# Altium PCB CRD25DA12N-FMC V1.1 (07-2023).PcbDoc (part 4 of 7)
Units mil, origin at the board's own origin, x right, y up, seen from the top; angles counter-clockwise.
Board outline 8000 x 8000 mil, 6 copper layers (Top Layer, Layer 2, Layer 3, Layer 4, Layer 5, Bottom Layer), stack 91 mil thick; 542 components, 315 nets, 1585 pads, 558 vias.
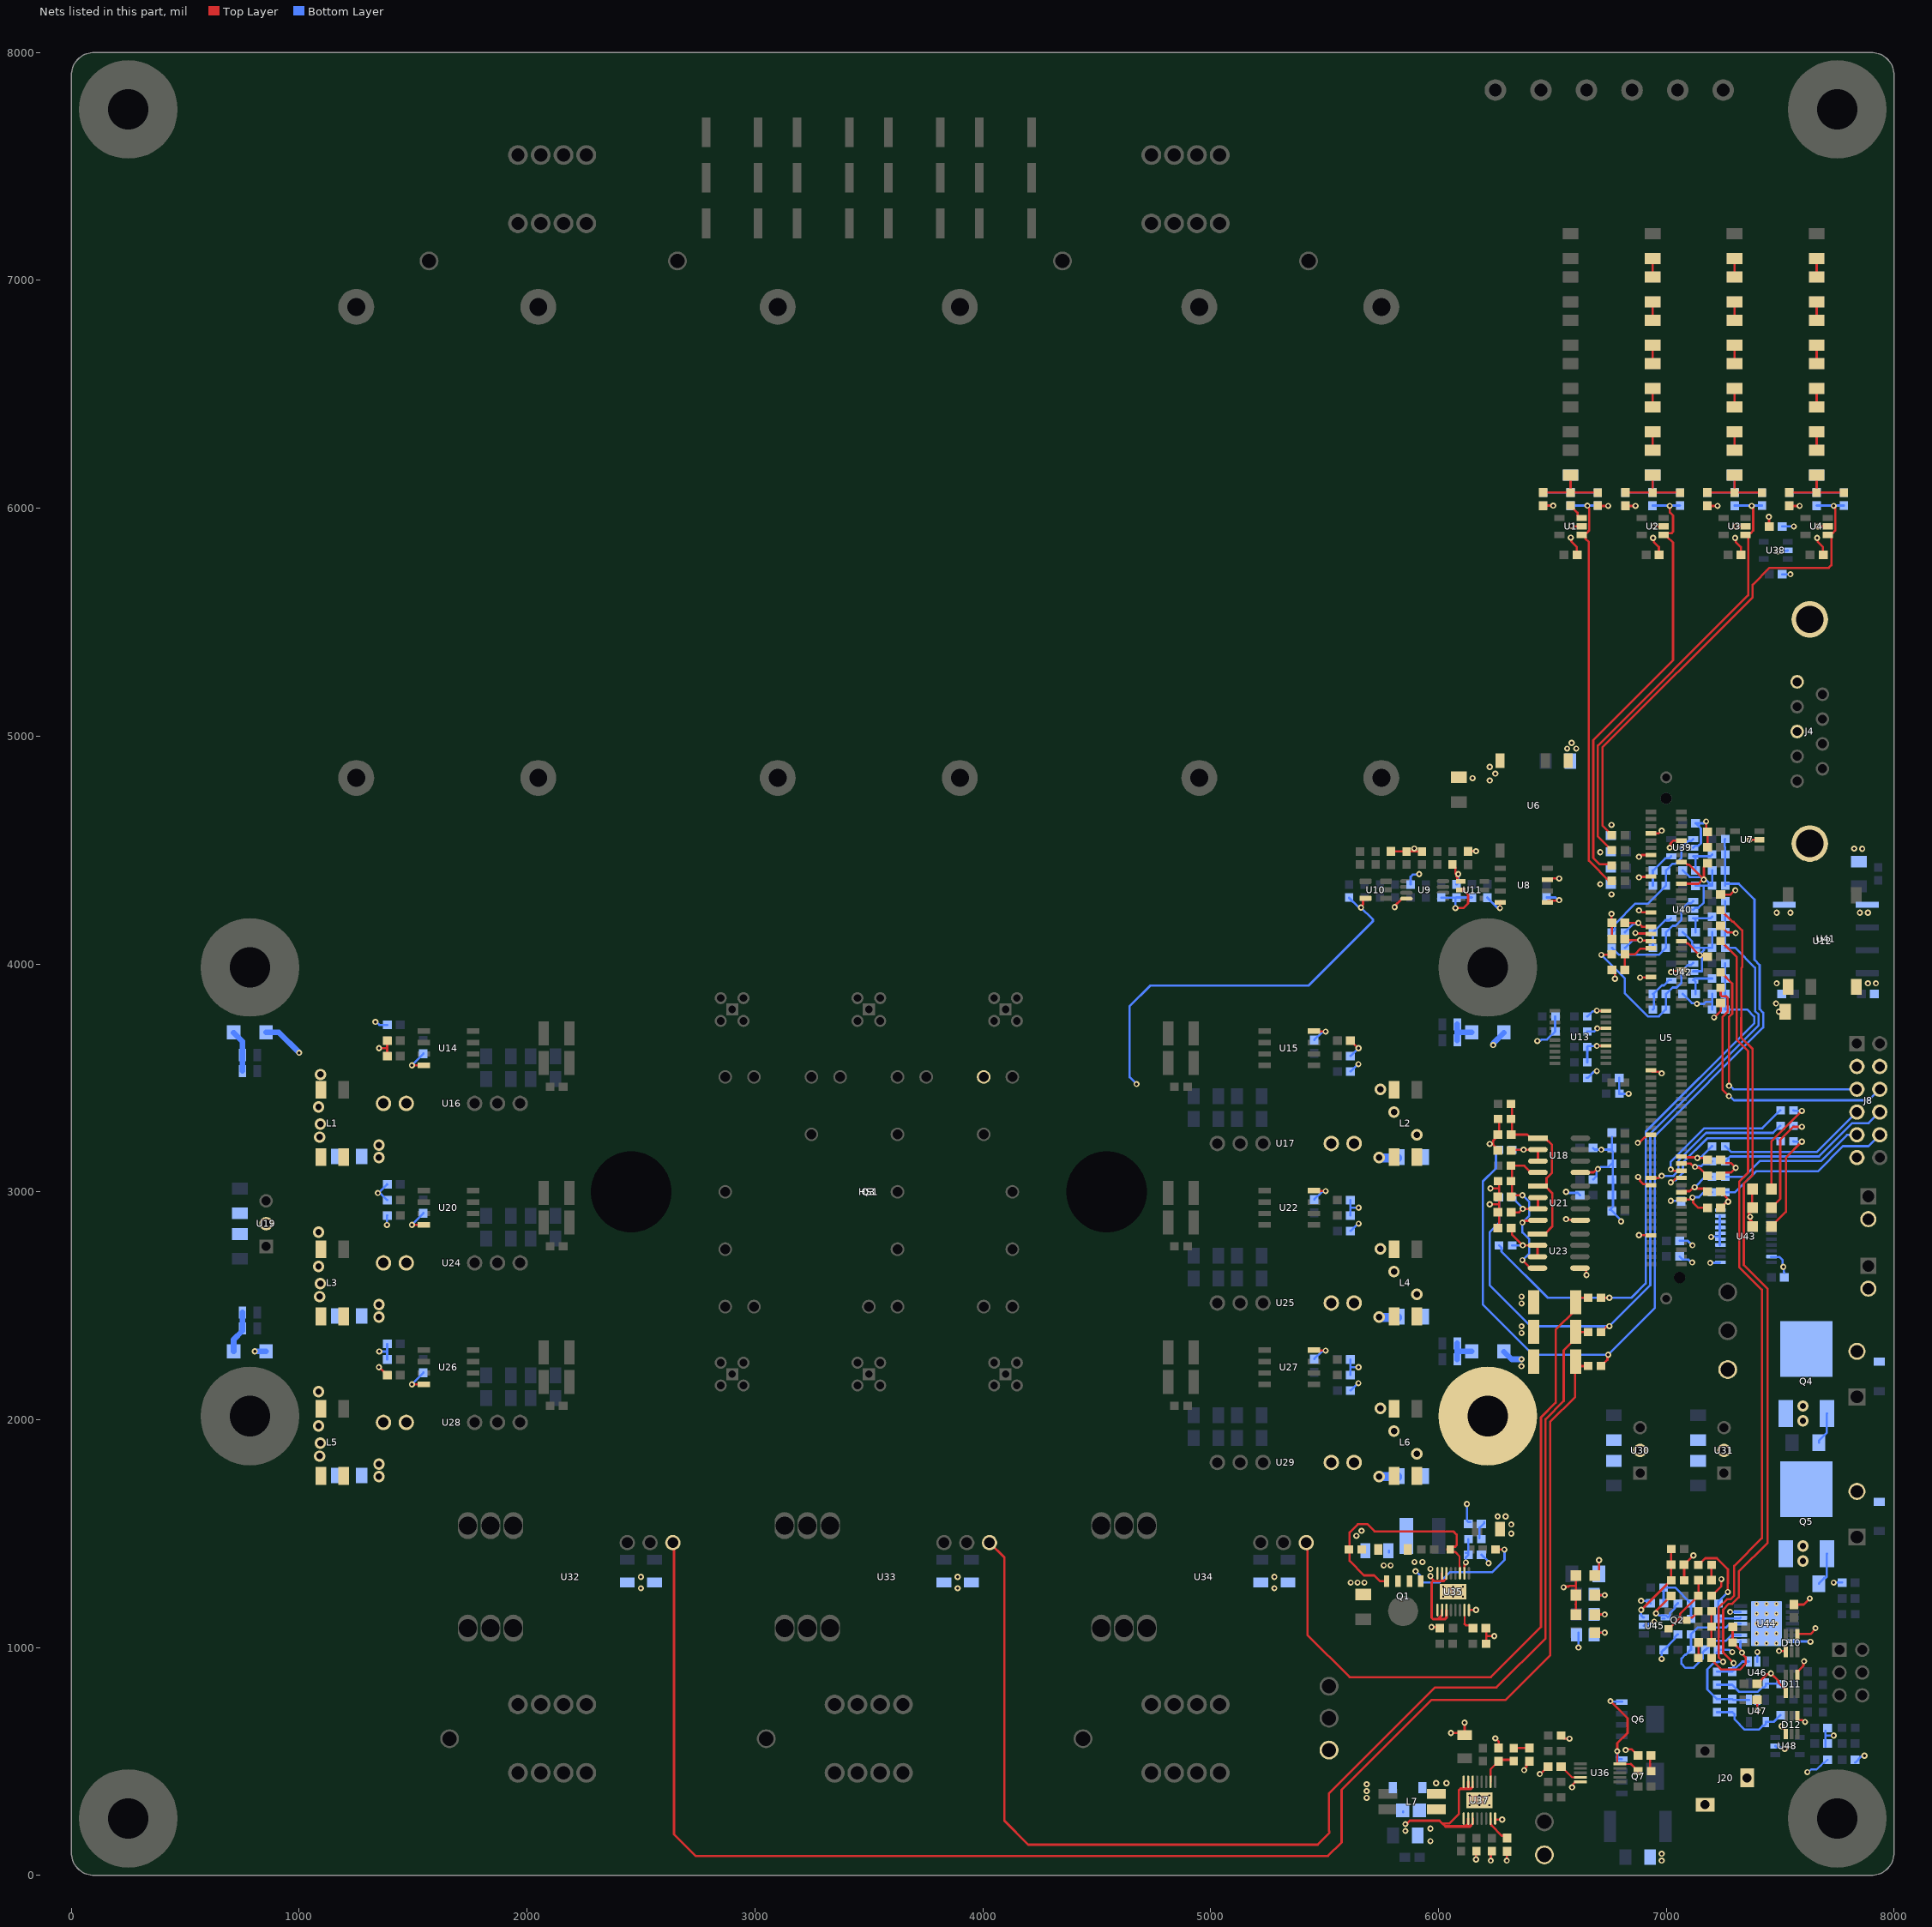
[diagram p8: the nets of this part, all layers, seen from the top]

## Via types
v1: diameter 27, hole 13, Top Layer to Bottom Layer, tented both sides, 455 vias
v2: diameter 50, hole 28, Top Layer to Bottom Layer, tented both sides, 76 vias
v3: diameter 19.68, hole 7.87, Top Layer to Bottom Layer, 27 vias

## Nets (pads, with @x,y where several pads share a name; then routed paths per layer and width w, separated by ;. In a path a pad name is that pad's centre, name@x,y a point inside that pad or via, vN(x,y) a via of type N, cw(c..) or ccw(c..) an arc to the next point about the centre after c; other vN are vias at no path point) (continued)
GND: C1.2 C2.2 C3.2 C4.2 C5.2 C6.2 C7.2 C8.2 C9.2 C11.2 C12.2 C15.2 C16.2 C17.2 C18.2 C19.2 C20.2 C21.2 C22.2 C23.2 C24.2 C25.2 C26.2 C27.2 C28.2 C29.2 C30.2 C31.2 C32.2 C33.2 C34.2 C35.2 C36.2 C37.2 C38.2 C40.2 C42.2 C44.2 C46.2 C47.2 C48.2 C49.2 C50.2 C51.2 C52.2 C53.2 C61.2 C62.2 C63.2 C64.2 C65.2 C66.2 C68.2 C69.2 C70.2 C72.2 C73.2 C77.2 C78.2 C79.2 C81.2 C83.2 C84.2 C85.2 C87.2 C88.2 C89.2 C90.2 C93.2 C94.2 C95.2 C102.2 C103.2 C104.2 C107.2 C108.2 C109.2 C110.2 C111.2 C112.2 C113.2 C114.2 C115.2 C116.2 C117.2 C118.2 C119.2 C120.2 C121.2 C124.2 C125.2 C126.2 C129.2 C132.2 C137.2 C138.2 C139.2 C140.2 C141.2 C142.2 C145.2 C148.2 C149.2 C154.2 C155.2 C158.2 C159.2 C160.2 C161.2 C162.1 C163.2 C164.1 C165.2 C166.1 C167.2 C169.2 C171.2 C172.2 C177.2 C179.2 C180.2 C181.2 C183.2 C184.2 D1.1 D2.1 D3.1 D6.1 D7.1 D8.1 D10.1 D10.4 D11.1 D11.4 D12.1 D12.4 D13.1 D14.1 D15.1 D16.1 D19.1 HS1.3 J8.3 J8.4 J8.11 J9.2 J10.2 J20.2 J20.3 L1.2 L2.2 L3.2 L4.2 L5.2 L6.2 Q4.3 Q5.3 R38.1 R67.1 R73.1 R84.1 R86.1 R90.1 R102.1 R103.1 R106.1 R109.1 R111.1 R120.1 R121.1 R164.1 R169.1 R174.1 R176.1 R177.1 R179.1 R180.1 R184.1 R187.1 R189.1 R216.1 R218.1 TP7.1 TP13.1 TP15.1 U1.2 U2.2 U3.2 U4.2 U5.7 U5.10 U5.13 U5.16 U5.19 U5.22 U5.29 U5.35 U5.38 U5.46 U5.47 U5.65 U5.83 U5.97 U5.111 U6.1 U7.2 U8.5 U8.7 U12.1 U13.4 U13.7 U13.10 U14.4 U15.4 U18.5 U19.2 U20.4 U21.5 U22.4 U23.5 U26.4 U27.4 U30.2 U31.2 U35.16 U35.17 U36.5 U37.16 U37.17 U38.2 U39.2 U40.2 U41.4 U42.2 U43.1 U43.4 U43.5 U43.6 U43.7 U43.8 U43.9 U43.10 U43.19 U44.6 U44.14 U44.15 U45.2 U46.2 U47.2 U48.2 | length 12079.2
  Top Layer w8: v1(6586.82,386.82) 6590.45,390.45 6590.45,400.31 U36.5@6599.86,409.72 ; U36.5@6600.77,410.63 U36.5@6622.91,410.63
  Top Layer w10: v1(1350,2230) 1351.47,2230 1385.47,2196 C36.2@1386.42,2196 ; v1(1350.35,3630) 1386.42,3630 ; C26.2@1385.47,3596 C26.2@1386.42,3596 1386.42,3630 ; C24.2@1386.42,3664 1386.42,3630 ; v1(1495,2155) U26.4@1546.73,2155 ; v1(1495,2855) U20.4@1546.73,2855 ; v1(1495,3555) U14.4@1546.73,3555 ; U27.4@5453.27,2305 5454.37,2303.9 5503.9,2303.9 v1(5505,2302.8) ; U22.4@5453.27,3005 5454.37,3003.9 5503.9,3003.9 v1(5505,3002.8) ; U15.4@5453.27,3705 5454.37,3703.9 5503.9,3703.9 v1(5505,3702.8) ; C25.2@5613.58,3664 5614.53,3664 5648.53,3630 v1(5649.65,3630) ; C40.2@5665,1241.25 C40.2@5670,1236.25 ; v1(5970,1090) 6001.38,1090 R106.1@6006.38,1085 ; v1(6055,625) 6111.73,625 6115,621.73 v1(6115,670) ; 6140,1165 v1(6165,1165) ; v1(6165,70) R120.1@6165,108.54 ; C44.2@6209.53,1085 6210,1084.53 6210,1049.76 ; R109.1@6210,1015 6210,1049.76 ; v1(6225,2945) 6265.42,2945 6266.42,2944 ; v1(6228.62,3014.86) 6263.54,3014.86 6266.38,3012.02 ; v1(6230,65) R121.1@6230,108.54 ; v1(6245,1050) 6244.76,1049.76 6210,1049.76 ; v1(6250,601.46) 6265,586.46 C49.2@6265,558.54 ; 6255,245 v1(6280,245) ; C35.2@6266.42,2840 6266.42,2944 ; R73.1@6266.38,3046 6266.38,3012.02 ; R67.1@6266.38,3319 6266.42,3318.96 6266.42,3251 6265.47,3251 6251.61,3237.14 6251.61,3236.19 6240.73,3225.3 6240.73,3206.75 6262.47,3185 C28.2@6275,3185 ; v1(6300,65) C53.2@6300,104.49 ; v1(6376.63,461.63) 6376.63,466.23 6386.14,475.74 6386.14,487.56 C50.2@6400,501.42 ; v1(6445,445) 6447.47,445 6480.47,478 C52.2@6481.42,478 ; C1.2@6460,6011.42 v1(6503.58,6011.42) ; U8.5@6478.35,4275 6480.85,4277.5 6527.5,4277.5 v1(6530,4280) ; U8.7@6478.35,4375 v1(6530,4375) v1@6531.12,4373.88 ; R111.1@6538.62,614 6551.58,601.04 6573.96,601.04 v1(6575,600) ; v1(6549.72,1264.16) 6552.97,1267.41 6572.61,1267.41 6575.2,1270 6601.16,1270 6603.66,1272.5 ; v1(6560,2880) 6562.53,2877.47 6620.58,2877.47 U21.5@6623.06,2875 ; v1(6580.67,5871.13) 6583.92,5867.88 6583.92,5853.71 6607.63,5830 6607.63,5795.95 C6.2@6608.58,5795 ; v1(6583.58,5921.42) 6584.29,5920.71 6627.52,5920.71 U1.2@6628.23,5920 ; U36.5@6599.86,409.72 U36.5@6600.77,410.63 ; 6601.16,1190 6603.66,1187.5 ; D8.1@6603.66,1145 6603.66,1187.5 ; D6.1@6603.66,1315 6603.66,1272.5 ; U23.5@6621.11,2665 6642.71,2665 6648.68,2659.03 6648.68,2636.32 v1(6650,2635) ; U18.5@6623.06,3085 6623.41,3085.36 6680.76,3085.36 6695.4,3100 v1(6700,3100) ; v1(6695,3640) 6695.3,3640.3 6734.7,3640.3 U13.4@6735,3640.59 ; v1(6695,3795) 6695.43,3794.57 6734.57,3794.57 U13.10@6735,3794.13 ; v1(6697.19,3717.36) U13.7@6735,3717.36 ; R38.1@6700,6011.38 6701.38,6010 v1(6745,6010) ; v1(6760,4220) 6760,4181.42 C17.2@6761.42,4180 C19.2@6761.42,4110 ; C21.2@6761.42,3974 6775,3960.42 v1(6775,3935) ; C2.2@6820,6011.42 6821.42,6010 v1(6865,6010) ; v1(6821.63,550.23) 6826.23,550.23 6830,554 6847.47,554 6875.47,526 C51.2@6876.42,526 ; v1(6864.55,4135.68) 6866.54,4133.69 6931.08,4133.69 U5.35@6933.07,4131.69 ; C51.2@6870.14,539.86 C51.2@6880,530 ; v1(6875,3215) 6878.25,3218.25 6884,3218.25 6904.89,3239.15 6908.64,3239.15 6919.29,3249.8 U5.83@6933.07,3249.8 ; v1(6876.5,3065) 6876.5,3060.4 6884.75,3052.15 6884.75,3048.22 6898.8,3034.17 6928.23,3034.17 U5.97@6933.07,3029.33 ; v1(6880,2810) 6880.57,2809.43 6929.43,2809.43 U5.111@6930,2810 ; v1(6880,4235) 6884.6,4235 6893.42,4226.18 U5.29@6933.07,4226.18 ; v1(6880,4380) 6881.83,4381.83 6931.24,4381.83 U5.19@6933.07,4383.66 ; v1(6880,4470) 6884.6,4470 6892.75,4478.15 U5.13@6933.07,4478.15 ; v1(6885,3940) 6885.47,3940.47 6934.53,3940.47 U5.47@6935,3940.94 ; U5.7@6933.07,4572.64 6966.29,4572.64 6978.65,4585 v1(6980,4585) ; U5.65@6935,3531.5 6939.84,3526.65 6968.75,3526.65 6975.4,3520 v1(6980,3520) ; v1(6942.09,5869.71) 6945.34,5866.45 6945.34,5852.28 6967.63,5830 6967.63,5795.95 C7.2@6968.58,5795 ; v1(6945,5920) U2.2@6988.23,5920 ; v1(7015,4510) 7018.25,4513.25 7018.25,4528.25 7031.14,4541.14 U5.10@7066.93,4541.14 ; v1(7021.31,3964.12) 7025.91,3964.12 7031.16,3969.37 7063.35,3969.37 U5.46@7067.64,3973.66 ; U5.38@7066.93,4100.2 7080.71,4100.2 7091.36,4089.54 7095.45,4089.54 v1(7147.18,4037.82) 7175.61,4037.82 C20.2@7181.42,4032 ; U5.22@7066.93,4352.17 7142.57,4352.17 7160.4,4370 v1(7165,4370) ; U5.16@7071.77,4451.5 U5.16@7066.93,4446.65 7080.71,4446.65 7091.36,4436 7099,4436 v1(7165,4370) ; v1(7118.8,1404.16) 7118.8,1402.28 7079.53,1363 C38.2@7078.58,1363 ; v1(7175,4625) 7175,4586.42 C11.2@7181.42,4580 C12.2@7181.42,4511 ; C3.2@7180,6011.42 7181.42,6010 v1(7225,6010) ; C15.2@7181.42,4442 7180.47,4442 7166.61,4428.14 7166.61,4427.19 7165,4425.58 v1(7165,4370) ; R103.1@7198.62,1227 7199.53,1227 7241.89,1269.36 v1(7241.89,1300) ; v1(7210,3765) 7240,3795 7240,3826.58 C22.2@7238.58,3828 ; C33.2@7238.58,2930 7239.53,2930 7262.82,2953.29 7268.25,2953.29 v1(7271.5,2956.54) 7268.25,2959.8 7268.25,2971.28 7239.53,3000 C31.2@7238.58,3000 ; C30.2@7238.58,3070 7235,3070 7230,3075 7238.86,3083.86 7283.86,3083.86 v1(7305,3105) 7283.86,3126.14 7252.44,3126.14 C29.2@7238.58,3140 ; C18.2@7238.58,4168 7239.53,4168 7269.27,4138.25 7301.75,4138.25 v1(7305,4135) ; C16.2@7238.58,4304 7281.99,4304 7301.26,4323.27 v1(7303.03,4323.27) ; v1(7302.09,5869.71) 7305.34,5866.45 7305.34,5852.28 7327.63,5830 7327.63,5795.95 C8.2@7328.58,5795 ; v1(7305,5920) U3.2@7348.23,5920 ; v1@7360.04,2893.32 7360,2893.28 7360,2885 D3.1@7375,2870 ; v1@7361.75,2883.25 v1(7368.5,2890) 7361.26,2897.24 7361.26,2911.38 7361.51,2911.63 D2.1@7372.7,2911.63 ; v1(7365,4545) U7.2@7408.15,4545 ; D2.1@7365.51,2949.17 7367.17,2949.17 D2.1@7367.17,2950.83 ; D2.1@7375,2948.66 7376.34,2950 D1.1@7376.34,3029.21 ; C47.2@7398.58,771 7400,769.58 v1(7400,725) ; C46.2@7398.58,840 7399.53,840 7442.79,883.26 7455.9,883.26 v1(7459.15,886.52) 7492.63,853.04 7492.63,846.19 7524.41,814.41 D11.1@7524.41,800.63 ; v1(7450,5962.36) 7451.14,5961.23 C5.2@7451.14,5920 ; v1(7495,985) 7520.55,985 7524.41,981.14 D10.1@7524.41,980.63 ; v1(7506,655.26) 7506,652.82 7520.55,638.27 D12.1@7520.55,625 ; C4.2@7540,6011.42 7541.42,6010 v1(7585,6010) ; C42.2@7560,1188.58 7603.58,1188.58 v1(7630,1215) ; D12.4@7575.59,699.37 7575.59,685.59 7579.45,681.73 7597.67,681.73 7605.4,674 v1@7610,674 ; D11.4@7575.59,879.37 7575.59,893.15 7601.75,919.31 7601.75,936.75 v1(7605,940) ; D10.4@7575.59,1059.37 7633.25,1059.37 7655,1081.12 v1(7655,1085) ; v1(7662.09,5869.71) 7665.34,5866.45 7665.34,5852.28 7687.63,5830 7687.63,5795.95 C9.2@7688.58,5795 ; v1(7665,5920) U4.2@7708.23,5920 ; 6266.42,2944 6266.42,2978 6266.38,2978.04 6266.38,3012.02 ; 6603.66,1187.5 D7.1@6603.66,1230 6603.66,1272.5 ; C38.2@7078.58,1363 R102.1@7078.62,1295 R102.1@7078.62,1295 C38.2@7078.58,1363
  Bottom Layer w8: v1@7623.76,452.95 7635.81,465 7660,465 7674.14,479.14 7675.38,479.14 7681.24,485 7681.24,486.24 7688.14,493.14 7693.71,493.14 C181.2@7708.58,508
  Bottom Layer w10: v1(1334.48,3745.52) 1338.09,3745.52 1351.61,3732 C87.2@1386.42,3732 ; v1(1351.47,2299.13) 1385.3,2299.13 1386.42,2298 ; v1(1385,2854.54) 1385,2894.58 C120.2@1386.42,2896 ; C137.2@1385.47,2332 C137.2@1386.42,2332 1386.42,2298 ; C138.2@1386.42,2264 1386.42,2298 ; C115.2@1386.42,2964 1385.47,2964 1357.73,2991.75 1348.25,2991.75 v1(1345,2995) 1348.47,2995 1385,3031.53 1385,3033.42 C110.2@1386.42,3032 ; v1(1495,2155) 1495,2155.47 1545,2205.47 C141.2@1545,2206.42 ; v1(1495,2855) 1495,2855.47 1545,2905.47 C118.2@1545,2906.42 ; v1(1495,3555) 1495,3555.47 1545,3605.47 C89.2@1545,3606.42 ; C140.2@5455,2265.58 5455,2266.53 5488.02,2299.54 5501.75,2299.54 v1(5505,2302.8) ; C117.2@5455,2965.58 5455,2966.53 5488.02,2999.54 5501.75,2999.54 v1(5505,3002.8) ; C88.2@5455,3665.58 5455,3666.53 5488.02,3699.54 5501.75,3699.54 v1(5505,3702.8) ; C145.2@5613.58,2128 5614.53,2128 5646.53,2160 v1(5649.05,2160) ; C142.2@5613.58,2196 5613.58,2230 ; C139.2@5613.58,2264 5613.58,2230 ; C124.2@5613.58,2828 5614.53,2828 5646.53,2860 v1(5650,2860) ; C121.2@5613.58,2896 5613.58,2930 ; C116.2@5613.58,2964 5613.58,2930 ; C93.2@5613.58,3528 5614.53,3528 5646.53,3560 v1(5649.05,3560) ; C90.2@5613.58,3596 5614.53,3596 5648.53,3630 v1(5649.65,3630) ; v1(5649.65,2230) 5649.5,2230.15 5621.15,2230.15 5621,2230 5613.58,2230 ; v1(5649.85,2930.15) 5649.69,2930 5613.58,2930 ; v1(6125,1630) 6125,1556.86 6131.51,1550.35 C158.2@6139.73,1550.35 ; C160.2@6188.58,1407 6189.53,1407 6216.75,1379.78 6216.75,1373.25 v1(6220,1370) ; D15.1@6287.4,2298.03 D15.1@6287.4,2300 ; D13.1@6287.4,3698.03 D13.1@6287.4,3700 ; D15.1@6311.93,2273.5 D15.1@6313.9,2273.5 ; v1@6361.45,2237.96 v1(6364.7,2234.7) ; v1(6433.85,3661.83) 6437.11,3665.08 6449.78,3665.08 6453.19,3668.5 6476.84,3668.5 6511.34,3703 6512.24,3703 R177.1@6512.24,3770 ; C73.2@6475,4291.42 6513.98,4291.42 6525.4,4280 v1(6530,4280) ; v1(6560,3000) 6564.6,3000 6569.6,2995 6611.42,2995 C114.2@6621.42,2985 ; v1@6583.57,390.07 v1(6586.82,386.82) ; R216.1@6614.49,1065 6615,1064.49 v1(6615,1000) ; C95.2@6650,3500 6654.53,3500 6681.27,3526.75 6691.75,3526.75 v1(6695,3530) ; R187.1@6653.62,3568 R184.1@6653.62,3636 6657.62,3640 v1(6695,3640) ; R179.1@6653.62,3703 6682.82,3703 v1(6697.19,3717.36) ; R176.1@6653.62,3770 6654.53,3770 6676.27,3791.75 6691.75,3791.75 v1(6695,3795) ; C109.2@6678.58,3054 6679.53,3054 6693.39,3067.86 6693.39,3088.79 6700,3095.4 v1(6700,3100) 6704.6,3100 6713.74,3109.14 6747.56,3109.14 C107.2@6761.42,3123 ; C104.2@6678.58,3192 6685.58,3185 v1(6715,3185) 6756.46,3185 C103.2@6761.46,3180 ; 6761.46,3240 C103.2@6761.46,3180 ; C94.2@6793.58,3500 R189.1@6793.62,3430 R189.1@6793.62,3430 v1(6835,3430) ; v1(6801.5,2870) 6798.25,2873.25 6798.25,2879.13 6756.07,2921.3 6752.76,2921.3 6766.46,2935 6766.46,3055.63 6765,3057.09 6765,3176.46 C103.2@6761.46,3180 ; v1(6889.85,1205.15) 6920.27,1205.15 C169.2@6931.42,1194 ; U45.2@6901.77,1095 6910.55,1103.78 6932.8,1103.78 6942.81,1113.79 v1(6947.41,1113.79) ; v1(6980,950) 6980,981.42 C172.2@6988.58,990 6989.53,990 7037.52,1037.99 7037.52,1045.04 7050.47,1058 R218.1@7051.38,1058 ; v1(7019.81,2960) 7062.85,2960 C111.2@7065,2957.85 ; C129.2@7058.58,2716 7072.44,2702.14 7097.31,2702.14 7109.45,2690 v1(7114.05,2690) ; C126.2@7058.58,2785 7094.69,2785 7114.69,2765 v1(7115,2765) ; C85.2@7071.42,3868 7072.37,3868 7112.12,3828.25 7131.75,3828.25 v1(7135,3825) 7166,3825 7175.02,3834.02 7201.42,3834.02 ; C79.2@7071.42,4139 7072.37,4139 7113.76,4097.61 7113.76,4083.86 7127.63,4070 C81.2@7128.58,4070 7164.98,4070 ; C70.2@7071.42,4411 7072.37,4411 7102.24,4381.14 7150.33,4381.14 7161.47,4370 v1(7165,4370) 7168.25,4366.75 7176.73,4366.75 R164.1@7200.47,4343 ; U42.2@7118.23,3967 7119.23,3968.01 7156.78,3968.01 7156.78,4023.62 7147.18,4033.22 v1(7147.18,4037.82) 7147.18,4042.42 7164.98,4060.21 7164.98,4070 ; U40.2@7118.23,4238 7127.01,4246.78 7141.58,4246.78 7164.52,4269.72 7164.52,4343 ; U39.2@7118.23,4510 7127.01,4518.78 7141.58,4518.78 7151.87,4529.07 7151.87,4594.66 C64.2@7129.53,4617 ; C77.2@7128.58,4343 7164.52,4343 ; C64.2@7128.58,4617 C64.2@7129.53,4617 ; v1(7175,4625) 7170.4,4625 7162.4,4617 C64.2@7129.53,4617 ; v1(7193.1,2688.1) 7193.46,2688.46 7234.64,2688.46 U43.1@7235,2688.82 ; v1(7196.63,2801.63) 7198.98,2803.98 7235,2803.98 ; R174.1@7201.38,3800 R174.1@7201.38,3800 7201.42,3834.02 ; C84.2@7201.42,3868 7201.42,3834.02 ; C78.2@7201.42,4139 C78.2@7201.42,4139 R169.1@7201.38,4070 7164.98,4070 ; C69.2@7201.42,4411 C69.2@7201.42,4411 R164.1@7201.38,4343 R164.1@7200.47,4343 ; C171.2@7220.28,975.24 C171.2@7230.05,985 ; C171.2@7228.58,990 7275.4,990 7285.4,980 v1(7290,980) ; U43.4@7235,2765.59 7235,2803.98 ; U43.9@7235,2893.54 7235,2803.98 ; U43.10@7235,2919.13 7246.97,2919.13 7249.85,2922.01 7249.85,2939.85 7252.01,2942.01 7252.36,2942.01 7266.9,2956.54 v1(7271.5,2956.54) ; v1(7280.29,1156.3) 7280.35,1156.24 U44.6@7325.83,1156.18 U44.6@7325.83,1156.18 ; v1(7400,725) U47.2@7400,770 ; U46.2@7400,938.23 v1(7400,980) ; U43.19@7459.41,2714.41 7495.59,2714.41 7510.88,2699.12 7510.88,2673.19 v1(7513.45,2670.62) 7516.7,2667.37 7516.7,2646.84 7518.54,2645 ; U48.2@7478.7,567.6 7485.51,560.79 7509.61,560.79 7515.4,555 v1(7520,555) ; v1(7490,5810) 7492.5,5812.5 7530.65,5812.5 U38.2@7533.15,5815 ; C62.2@7508.58,5710 v1(7545,5710) ; C61.2@7508.58,5920 v1(7560,5920) ; U44.14@7554.17,1028.23 7555.63,1026.77 7631.32,1026.77 v1(7632.78,1025.32) ; v1(7619.16,452.95) v1@7623.76,452.95 ; C179.2@7698.58,565 7698.58,599.5 ; C177.2@7698.58,634 7698.58,616.75 ; 7699.08,600 7698.58,599.5 ; v1(7734.95,613.44) 7701.89,613.44 7698.58,616.75 ; v1(7735,1285) C167.2@7771.42,1285 ; C180.2@7828.58,495 7829.53,495 7856.27,521.75 7866.75,521.75 v1(7870,525) ; 7164.52,4343 R164.1@7200.47,4343 ; 7698.58,599.5 7698.58,616.75
  Bottom Layer w25: v1(805,2300) D16.1@854.33,2300 ; D14.1@854.33,3700 910,3700 v1(1000,3610) ; v1(6240.35,3644.22) 6240.73,3644.6 6240.73,3651.36 D13.1@6287.4,3698.03 ; D15.1@6287.4,2298.03 D15.1@6311.93,2273.5 ; D15.1@6313.9,2273.5 6322.4,2265 v1(6365,2265)
  other v1: 6980,65 6980,95 5965,150 5965,205 5685,340 5685,370 5685,400 7609.25,673.1 2500,1260 3890,1260 5280,1260 5615,1285 5645,1285 5675,1285 2500,1310 3890,1310 5280,1310 5639.85,1490.15 6320,1500 5662.8,1512.2 6320,1540 6260,1575 6295,1575 6365,2380 6364.85,2409.85 6365,2510 6365,2540 6225,3210 7494.21,3790 7481.72,3826.72 7485,3915 7485,4225 7545,4225 6760,4305 6710,4350 6710,4490 6760,4610 6565,4945 6605,4945 6585,4970
  other v2: 7600,1380 7600,1445 5805,1950 1085,1972 7600,1994.76 5745,2050 7600,2059.76 1085,2123 5805,2650 1085,2672 5745,2750 1085,2823 5805,3350 1085,3372 5745,3450 1093.14,3514.86
  other v3: 6136.69,308.35 6180,308.35 6223.31,308.35 6136.69,351.65 6180,351.65 6223.31,351.65 7396.69,1018.39 7440,1018.39 7483.31,1018.39 7396.69,1061.69 7440,1061.69 7483.31,1061.69 7396.69,1105 7440,1105 7483.31,1105 7396.69,1148.31 7440,1148.31 7483.31,1148.31 7396.69,1191.61 7440,1191.61 7483.31,1191.61 6021.69,1223.35 6065,1223.35 6108.31,1223.35 6021.69,1266.65 6065,1266.65 6108.31,1266.65
GND_ISO: C67.2 C82.2 J4.3 J4.5 J4.10 J4.11 U12.4 U41.5
  other v1: 7885,3915 7920,3915 7850,4225 7885,4225 7860,4505 7824.6,4506.19
GND_NTC: C10.2 C13.2 C14.2 C74.2 C75.2 C76.2 Q3.NTC1 R49.1 R50.1 R157.1 R159.1 R163.1 U6.4 U8.4 U9.4 U10.5 U11.2 | length 2565.5
  Top Layer w10: v1(5660.12,4247.58) 5660.12,4252.18 5668.94,4261 5668.94,4280.98 5675.55,4287.6 U10.5@5689.92,4287.6 ; C13.2@5792,4493.58 R49.1@5860,4493.62 R49.1@5860,4493.62 v1@5894,4493.62 ; v1(5808.01,4249.02) 5811.27,4252.27 5811.27,4257.51 5837.96,4284.2 5856.88,4284.2 U9.4@5859.29,4286.61 ; v1(5894,4506.31) v1@5894,4493.62 ; R50.1@5928,4493.62 v1@5894,4493.62 ; v1(6075,4245) 6110.4,4245 6130.49,4265.09 6130.49,4303.17 6108.66,4325 U11.2@6098.82,4325 ; C14.2@6130,4493.58 6131.42,4495 v1(6165,4495) ; v1(6270,4245) 6270,4273.35 U8.4@6271.65,4275
  Bottom Layer w10: v1(4675,3472.73) 4645,3502.73 4645,3815 4735,3905 5430,3905 5712.21,4187.21 5712.21,4195.49 5656.87,4250.83 5647.64,4250.83 5608,4290.47 R163.1@5608,4291.38 ; R159.1@5878,4348.62 5878,4382.48 5887.25,4391.73 5913.47,4391.73 v1(5915.75,4394.02) ; R157.1@6012,4291.38 C76.2@6079,4291.42 ; v1(6075,4245) 6075,4287.42 C76.2@6079,4291.42 ; C75.2@6147,4291.42 C76.2@6079,4291.42 C76.2@6079,4291.42 ; C74.2@6225,4281.42 C74.2@6215,4291.42 6215,4290.47 6257.22,4248.25 6266.75,4248.25 v1(6270,4245)
  other v1: 6225,4805 6150,4815 6250,4835 6225,4865
GPIO35: C29.1 R193.2 U5.90 | length 202.3
  Top Layer w10: U5.90@7066.93,3155.31 7070.74,3151.5 v1@7133.49,3151.51 ; v1(7136.75,3148.25) 7173.17,3148.25 C29.1@7181.42,3140
  Bottom Layer w10: v1(7136.75,3148.25) 7140,3151.51 7151.98,3151.51 7200.47,3200 R193.2@7201.38,3200
GPIO44: C30.1 R195.2 U5.92 | length 222
  Top Layer w10: U5.92@7066.93,3123.82 7106.98,3123.82 7121.23,3109.57 v1(7125.83,3109.57) 7129.08,3106.32 7144.15,3106.32 7180.47,3070 C30.1@7181.42,3070
  Bottom Layer w10: v1(7125.83,3109.57) 7129.08,3112.83 7154.15,3112.83 7161.37,3120.04 7188.42,3120.04 R195.2@7201.38,3133
GPIO54: C31.1 R196.2 U5.100 | length 227.4
  Top Layer w10: U5.100@7066.93,2997.83 7071.77,3002.68 7103.08,3002.68 7120.4,3020 v1(7125,3020) 7129.6,3020 7135.74,3013.86 7167.56,3013.86 C31.1@7181.42,3000
  Bottom Layer w10: v1(7125,3020) 7171,3066 R196.2@7201.38,3066
GPIO55: C33.1 R197.2 U5.102 | length 232.1
  Top Layer w10: U5.102@7066.93,2966.34 7101.74,2966.34 ; v1@7118.25,2978.25 v1(7115,2975) 7118.25,2971.75 7118.25,2951.75 7140,2930 C33.1@7181.42,2930
  Bottom Layer w10: v1(7115,2975) 7116.44,2976.44 7143.5,2976.44 7165.06,2998 R197.2@7201.38,2998
HI_OC_REF: C27.1 R66.1 R67.2 U18.1 U21.1 U23.1 | length 820.8
  Top Layer w10: R66.1@6323.62,3386 6323.62,3319 6323.62,3251.04 6323.58,3251 6389.7,3251 6405.7,3235 U18.1@6436.94,3235 6468.19,3235 6498.19,3205 6498.19,3083.24 6474.64,3059.7 6474.64,3031.46 U21.1@6468.19,3025 ; U23.1@6435,2815 6466.24,2815 6500,2848.76 6500,2993.19 U21.1@6468.19,3025 ; U21.1@6436.94,3025 U21.1@6468.19,3025
IU: R90.2 R93.1 U32.9 | length 7064.2
  Top Layer w10: U32.9@2640,1460 2645,1455 2645,180 2740,85 5515,85 5575,145 5575,375 5970,770 6295,770 6490,965 6490,1990 6600,2100 6600,2252.48 R90.2@6602.52,2255 ; R90.2@6602.52,2254.61 6622.13,2235 R93.1@6656.38,2235
IU_FILT: C69.1 R93.2 R154.1 R155.1 R164.2 R194.1 | length 4074.7
  Top Layer w10: R93.2@6713.62,2235 6714.53,2235 6741.75,2262.22 6741.75,2281.75 v1(6745,2285)
  Bottom Layer w10: R194.1@6265.47,3185 6252.52,3172.04 6252.52,3102.52 6195,3045 6195,2505 6415,2285 v1(6745,2285) 6950,2490 6950,3245.31 7425.71,3721.02 7425.71,3785.85 7410,3801.57 7410,3995 7387,4018 7387,4283 7318.23,4351.77 7260.39,4351.77 R164.2@7258.62,4350 ; R164.2@7258.62,4343 R164.2@7258.62,4350 ; R154.1@7258.62,4548 7255.96,4545.33 7255.96,4515.04 7258.62,4512.38 R155.1@7258.62,4480 R155.1@7258.62,4480 C69.1@7258.58,4411 C69.1@7258.58,4411 R164.2@7258.62,4350
IU_MEAS: C17.1 R168.2 U5.33 | length 197.7
  Top Layer w10: C17.1@6818.58,4180 v1(6877.48,4180) 6894.45,4163.03 U5.33@6933.39,4163.03
  Bottom Layer w10: R168.2@6818.62,4139 6819.53,4139 6857.27,4176.75 6874.22,4176.75 v1(6877.48,4180)
IV: R86.2 R87.1 U33.9 | length 5597.3
  Top Layer w10: U33.9@4030,1460 4095,1395 4095,240 4200,135 5470,135 5520.86,185.86 5520.86,194.14 5520,195 5520,360 5985,825 6255,825 6470,1040 6470,2001.72 6550,2081.72 6550,2303.94 6602.52,2356.46 R86.2@6602.52,2385 R87.1@6656.38,2385
IV_FILT: C78.1 R87.2 R166.1 R167.1 R169.2 R198.1 | length 3272.5
  Top Layer w10: R87.2@6713.62,2385 6714.53,2385 6736.27,2406.75 6746.75,2406.75 v1(6750,2410)
  Bottom Layer w10: R198.1@6266.46,2975 6266.46,2863.91 6225,2822.45 6225,2590 6405,2410 v1(6750,2410) 6930,2590 6930,3255 7405.71,3730.71 7405.71,3777.57 7390,3793.28 7390,3983.81 7303.81,4070 R169.2@7258.62,4070 C78.1@7258.58,4139 C78.1@7258.58,4139 C78.1@7258.58,4139 R167.1@7258.62,4207 R166.1@7258.62,4275
IV_MEAS: C19.1 R171.2 U5.37 | length 208.3
  Top Layer w10: C19.1@6809.06,4104.85 v1(6885,4104.85) 6887.32,4102.52 6930.9,4102.52 U5.37@6934.21,4099.21
  Bottom Layer w10: R171.2@6818.62,4070 6819.53,4070 6854.37,4104.85 v1(6885,4104.85)
IW: R84.2 R85.1 U34.9 | length 3137
  Top Layer w10: U34.9@5420,1460 5425,1455 5425,1055 5610,870 6230,870 6450,1090 6450,2010 6515,2075 6515,2393.94 6602.52,2481.46 R84.2@6602.52,2505 ; R84.2@6602.52,2510 R84.2@6607.52,2505 ; R84.2@6607.52,2535 R85.1@6659.41,2535
IW_FILT: C84.1 R85.2 R172.1 R173.1 R174.2 R199.1 | length 2525
  Top Layer w10: R85.2@6710.59,2535 R85.2@6713.62,2535 v1(6750,2535)
  Bottom Layer w10: R199.1@6266.46,2765 6277.1,2754.36 6277.1,2737.9 6480,2535 v1(6750,2535) 6846.72,2535 6910,2598.28 6910,3263.28 7385.71,3739 7385.71,3769.29 7355,3800 R174.2@7258.62,3800 R174.2@7258.62,3800 C84.1@7258.58,3868 R173.1@7258.62,3936 R173.1@7258.62,3936 R172.1@7258.62,4003
IW_MEAS: C21.1 R57.2 U5.39 | length 194.9
  Top Layer w10: C21.1@6818.58,3974 R57.2@6818.62,4042 R57.2@6818.62,4042 6861.55,4042 6886.48,4066.93 6935,4066.93 U5.39@6934.85,4066.78
LED_G: R192.2 U5.96 | length 648.6
  Top Layer w10: v1(7019.92,3041.5) 7024.52,3041.5 7039.01,3055.98 7062.09,3055.98 U5.96@7066.93,3060.83
  Bottom Layer w10: v1(7019.92,3041.5) 7024.52,3041.5 7033.02,3050 7040.09,3050 7073.19,3083.1 7073.19,3128.49 7179.69,3235 7410,3235 7410.04,3234.96 7488.42,3234.96 R192.2@7501.38,3222
LED_R: R190.2 U5.94 | length 657.9
  Top Layer w10: v1(7020,3098.5) 7024.6,3098.5 7030.78,3092.32 U5.94@7066.93,3092.32
  Bottom Layer w10: v1(7020,3098.5) 7020,3131.87 7166.56,3278.44 7420.91,3278.44 7500.47,3358 R190.2@7501.38,3358
LED_Y: R191.2 U5.95 | length 690.2
  Top Layer w10: U5.95@6933.07,3060.83 6933.48,3060.41 6966.29,3060.41 6975.88,3070 v1(6980,3070)
  Bottom Layer w10: v1(6980,3070) 7031.81,3070 7053.19,3091.38 7053.19,3136.77 7174.85,3258.44 7468.91,3258.44 7500.47,3290 R191.2@7501.38,3290
LO_OC_REF: C32.1 R71.1 R73.2 U18.4 U21.4 U23.4 | length 797.1
  Top Layer w10: v1(6368.62,2699.86) 6368.76,2699.86 6403.62,2665 U23.4@6435,2665 ; v1(6368.62,2864.86) 6373.22,2864.86 6380.89,2872.53 6434.47,2872.53 U21.4@6436.94,2875 ; v1(6368.62,2984.86) 6330.44,2984.86 6323.58,2978 6323.58,3045.96 6323.62,3046 6323.62,3114 6376.7,3114 6405.7,3085 U18.4@6436.94,3085
  Bottom Layer w10: v1(6368.62,2699.86) 6398.5,2729.74 6398.5,2791.79 6368.62,2821.67 v1(6368.62,2864.86) 6398.5,2894.74 6398.5,2954.98 v1(6368.62,2984.86)
MOD: C76.1 R52.1 U11.1 | length 140.4
  Top Layer w10: R52.1@6071.09,4426.38 6074.96,4422.52 6074.96,4396.23 6078.48,4392.7 6078.48,4384.62 6083.15,4379.95 6083.15,4368.23 6088.98,4362.4 U11.1@6098.82,4362.4 ; v1@6078.69,4384.41 v1@6086.98,4392.7
  Bottom Layer w10: C76.1@6079,4348.58 6086.98,4356.56 v1@6086.98,4392.7
  other v1: 6086.98,4394
NetC1_1: C1.1 R33.2 R37.1 R38.2 | length 316.3
  Top Layer w10: C1.1@6460,6068.58 R37.1@6580,6068.62 R37.1@6580,6068.62 ; R33.2@6580,6144.88 R37.1@6580,6068.62 ; R38.2@6700,6068.62 R37.1@6580,6068.62
NetC2_1: C2.1 R34.2 R39.1 R40.1 | length 316.3
  Top Layer w10: C2.1@6820,6068.58 R39.1@6940,6068.62 R39.1@6940,6068.62 ; R34.2@6940,6144.88 R39.1@6940,6068.62 ; R40.1@7060,6068.62 R39.1@6940,6068.62
NetC3_1: C3.1 R35.2 R41.1 R42.1 | length 316.3
  Top Layer w10: C3.1@7180,6068.58 R41.1@7300,6068.62 R41.1@7300,6068.62 ; R35.2@7300,6144.88 R41.1@7300,6068.62 ; R42.1@7420,6068.62 R41.1@7300,6068.62
NetC4_1: C4.1 R36.2 R43.1 R44.1 | length 316.3
  Top Layer w10: C4.1@7540,6068.58 C4.1@7540,6068.58 R43.1@7660,6068.62 ; R36.2@7660,6144.88 R43.1@7660,6068.62 ; R44.1@7780,6068.62 R43.1@7660,6068.62
NetC28_1: C28.1 R194.2 U18.2 U18.3 | length 210.1
  Top Layer w10: C28.1@6324.21,3185 6324.47,3184.74 v1(6374.09,3184.74) 6374.22,3184.87 6436.82,3184.87 U18.2@6436.94,3185 U18.3@6436.94,3135
  Bottom Layer w10: R194.2@6327.09,3185 6327.35,3184.74 v1(6374.09,3184.74)
NetC34_1: C34.1 R198.2 U21.2 U21.3 | length 239.4
  Top Layer w10: C34.1@6323.58,2910 6355,2910 v1(6370,2925) U21.3@6436.94,2925 U21.2@6436.94,2975
  Bottom Layer w10: R198.2@6323.54,2975 6324.53,2975 6370,2929.53 v1(6370,2925)
NetC35_1: C35.1 R199.2 U23.2 U23.3 | length 255.7
  Top Layer w10: C35.1@6323.58,2840 6323.58,2811.42 v1(6370,2765) U23.2@6435,2765 U23.3@6435,2715
  Bottom Layer w10: R199.2@6323.54,2765 R199.2@6323.62,2765 v1(6370,2765)
NetC38_1: C38.1 R97.1 R102.2 U45.3 | length 361.5
  Top Layer w10: v1(6890,1165) 6890.47,1165 7020.32,1294.85 7021.23,1294.85 R102.2@7021.38,1295 C38.1@7021.42,1363 C38.1@7021.42,1363 R97.1@7021.38,1432 R97.1@7021.38,1432
  Bottom Layer w10: v1(6890,1165) 6890,1141.18 6898.78,1132.4 U45.3@6901.77,1132.4
NetC39_1: C39.1 R101.1 | length 68
  Top Layer w10: C39.1@7198.58,1295 R101.1@7198.62,1363 R101.1@7198.62,1363
NetC39_2: C39.2 Q2.2 R103.2 | length 268.3
  Top Layer w10: Q2.2@7010.63,1082.6 7012.6,1082.6 7060.65,1130.65 7060.65,1147.18 7140.47,1227 R103.2@7141.38,1227 R103.2@7141.38,1227 C39.2@7141.42,1295
NetC41_2: C41.2 R212.1 U45.4 | length 259.2
  Top Layer w10: v1(6955,1150) 6958.25,1153.25 6958.25,1164.78 7018.42,1224.95 7018.42,1230 C41.2@7021.42,1227
  Bottom Layer w10: v1(6955,1150) 6959.6,1150 6968.42,1141.18 6998.31,1141.18 7007.09,1132.4 7015.87,1141.18 7015.87,1150.04 7037.52,1171.69 7037.52,1181.04 7050.47,1194 R212.1@7051.38,1194 ; U45.4@6983.23,1127.4 U45.4@6992.09,1127.4
NetC43_1: C43.1 R107.1 R110.2 U44.1 | length 438.5
  Top Layer w10: R110.2@7184.76,961.77 7243.14,903.39 7322.53,903.39 7348.5,929.36 7348.5,956.96 7332.39,973.07 7332.39,981.89 7292.28,1022 R107.1@7291.38,1022 C43.1@7291.42,1091 C43.1@7291.42,1091
  Bottom Layer w10: U44.1@7325.83,1028.23 7325.83,1025.2 7325,1024.37 7325,989.66 7332.39,982.27 v1(7332.39,977.67)
NetC44_1: C44.1 U35.15 | length 105
  Top Layer w8: 6115,1103.57 U35.15@6115,1164.29
  Top Layer w10: 6115,1103.57 6120.86,1097.72 6139.72,1097.72 6150.47,1086.97 C44.1@6150.47,1085
NetC45_1: C45.1 R110.1 | length 68.5
  Top Layer w10: R110.1@7141.38,954 R110.1@7141.38,954 C45.1@7141.42,1022 ; C45.1@7154.92,1024.17 C45.1@7155.24,1023.86
NetC45_2: C45.2 R104.2 R105.1 | length 149.2
  Top Layer w10: R104.2@7189.73,1151.02 7197.72,1159 R104.2@7198.62,1159 R105.1@7198.62,1091 R105.1@7198.62,1091 C45.2@7198.58,1022
NetC49_1: C49.1 R113.2 U37.2 | length 179.8
  Top Layer w8: U37.2@6229.21,409.25 6229.21,466.18 6263.76,500.73 C49.1@6268.03,505
  Top Layer w10: C49.1@6263.03,501.46 C49.1@6265,501.46 ; C49.1@6270,505 6272.36,507.36 R113.2@6335,507.36
NetC50_1: C50.1 R113.1 | length 69
  Top Layer w10: R113.1@6331,558.62 C50.1@6400,558.58 C50.1@6400,558.58
NetC51_1: C51.1 R115.1 | length 73.8
  Top Layer w10: C51.1@6929.21,530 6929.21,462.41 R115.1@6933.62,458
NetC52_1: C52.1 U36.4 | length 104.2
  Top Layer w8: C52.1@6538.58,478 6586.58,430 U36.4@6622.91,430
NetC53_1: C53.1 U37.15 | length 120.6
  Top Layer w10: U37.15@6229.21,247.83 6229.21,225.35 6232.98,221.59 6232.98,218.6 6277.29,174.29 6289.25,174.29 C53.1@6300,163.54
NetC57_1: C57.1 R142.2 R146.2 R147.1 | length 316.3
  Bottom Layer w10: R147.1@7540,6068.62 C57.1@7660,6068.58 ; R142.2@7660,6144.88 C57.1@7660,6068.58 ; R146.2@7780,6068.62 C57.1@7660,6068.58
NetC57_2: C57.2 R45.1 R146.1 U4.1 | length 2178.4
  Top Layer w10: R45.1@6761.38,4566 6720,4607.38 6720,4950 7379.39,5609.39 7379.39,5664.39 7453.5,5738.5 7713.5,5738.5 7725,5750 7725,5874.61 7712.62,5886.99 7717.01,5891.38 7731.58,5891.38 7741.87,5901.66 7741.87,5998.53 7735,6005.4 v1(7735,6010)
  Bottom Layer w10: C57.2@7660,6011.42 R146.1@7780,6011.38 R146.1@7780,6011.38
NetC58_1: C58.1 R143.2 R148.2 R149.1 | length 316.3
  Bottom Layer w10: R149.1@7180,6068.62 C58.1@7300,6068.58 C58.1@7300,6068.58 ; R143.2@7300,6144.88 C58.1@7300,6068.58 ; R148.2@7420,6068.62 R148.2@7420,6068.62 C58.1@7300,6068.58
NetC58_2: C58.2 R46.1 R148.1 U3.1 | length 1950.8
  Top Layer w10: R46.1@6751.46,4505 6751.46,4507.95 6700,4559.41 6700,4958.28 7359.39,5617.67 7359.39,5873.82 7350.61,5882.6 U3.1@7348.23,5882.6 7357.01,5891.38 7371.58,5891.38 7381.87,5901.66 7381.87,5998.53 7375,6005.4 v1(7375,6010)
  Bottom Layer w10: C58.2@7300,6011.42 C58.2@7300,6011.42 R148.1@7420,6011.38
NetC59_1: C59.1 R144.2 R150.2 R151.1 | length 316.4
  Bottom Layer w10: R151.1@6820,6068.62 R151.1@6820,6068.62 C59.1@6940,6068.58 C59.1@6940,6068.58 ; R144.2@6940,6144.88 C59.1@6940,6068.58 ; R150.2@7060,6068.62 C59.1@6940,6068.58 C59.1@6940,6068.58
NetC59_2: C59.2 R53.1 R150.1 U2.1 | length 1959
  Top Layer w10: R53.1@6761.38,4432 6756.23,4437.15 6707.85,4437.15 6680,4465 6680,4982.05 7030,5332.05 7030,5849.09 7005.87,5873.23 7005.87,5873.82 6992.95,5886.73 6992.36,5886.73 6996.5,5890.87 7024.13,5890.87 7029.99,5896.72 7029.99,5967.61 7016.1,5981.5 7016.1,6008.9 v1(7015,6010)
  Bottom Layer w10: C59.2@6940,6011.42 R150.1@7060,6011.38 R150.1@7060,6011.38
NetC60_1: C60.1 R145.2 R152.1 R153.1 | length 316.3
  Bottom Layer w10: R153.1@6460,6068.62 C60.1@6580,6068.58 C60.1@6580,6068.58 ; R145.2@6580,6144.88 C60.1@6580,6068.58 ; R152.1@6700,6068.62 R152.1@6700,6068.62 C60.1@6580,6068.58
NetC60_2: C60.2 R54.1 R152.2 U1.1 | length 1857.1
  Top Layer w10: v1(6653.58,6011.42) 6653.58,6006.82 6661.87,5998.53 6661.87,5901.66 6651.58,5891.38 6637.01,5891.38 U1.1@6628.23,5882.6 6637.09,5882.6 6645.87,5873.82 6645.87,5864.96 6660,5850.83 6660,4452.95 R54.1@6755,4357.95
  Bottom Layer w10: C60.2@6580,6011.42 v1(6653.58,6011.42) R152.2@6700,6011.38 R152.2@6700,6011.38
NetC70_1: C70.1 R155.2 U39.3 | length 151.5
  Bottom Layer w10: U39.3@7118.23,4472.6 U39.3@7119.8,4472.6 ; C70.1@7128.58,4411 7128.58,4463.82 U39.3@7119.8,4472.6 ; R155.2@7201.38,4480 7193.98,4472.6 U39.3@7119.8,4472.6
NetC71_1: C71.1 R165.1 U39.4 | length 173.9
  Bottom Layer w10: R165.1@6941.38,4343 C71.1@6941.42,4411 C71.1@6941.42,4411 6942.37,4411 6995.19,4463.82 7012.99,4463.82 U39.4@7021.77,4472.6
NetC71_2: C71.2 R165.2 R168.1 U39.1 | length 605.8
  Bottom Layer w10: R168.1@6761.38,4139 6762.28,4139 6775.24,4151.96 6775.24,4175.24 6865,4265 6919.72,4265 6997.72,4343 R165.2@6998.62,4343 C71.2@6998.58,4411 C71.2@6998.58,4411 6999.53,4411 7028.09,4439.56 7040.71,4439.56 7065.87,4464.73 7065.87,4509.62 7094.88,4538.62 7109.45,4538.62 U39.1@7118.23,4547.4
NetC79_1: C79.1 R167.2 U40.3 | length 151
  Bottom Layer w10: U40.3@7118.23,4200.6 U40.3@7119.8,4200.6 ; C79.1@7128.58,4139 7128.58,4191.82 U40.3@7119.8,4200.6 ; R167.2@7201.38,4207 7194.98,4200.6 U40.3@7119.8,4200.6
NetC80_1: C80.1 R170.1 U40.4 | length 174.9
  Bottom Layer w10: R170.1@6941.38,4070 C80.1@6941.42,4139 C80.1@6941.42,4139 6942.37,4139 6995.19,4191.82 7012.99,4191.82 U40.4@7021.77,4200.6
NetC80_2: C80.2 R170.2 R171.1 U40.1 | length 532.7
  Bottom Layer w10: R171.1@6761.38,4070 6762.28,4070 6791.24,4041.04 6968.76,4041.04 6997.72,4070 R170.2@6998.62,4070 C80.2@6998.58,4139 C80.2@6998.58,4139 6999.53,4139 7028.09,4167.56 7040.71,4167.56 7065.87,4192.73 7065.87,4237.62 7094.88,4266.62 7109.45,4266.62 U40.1@7118.23,4275.4
NetC85_1: C85.1 R173.2 U42.3 | length 152.6
  Bottom Layer w10: C85.1@7128.58,3868 7128.58,3920.82 7119.8,3929.6 7118.23,3929.6 7124.63,3936 R173.2@7201.38,3936
NetC86_1: C86.1 R175.1 U42.4 | length 177.7
  Bottom Layer w10: R175.1@6941.38,3800 6946.04,3804.67 6946.04,3863.38 C86.1@6941.42,3868 6942.37,3868 6980.52,3906.15 6989.46,3906.15 7012.91,3929.6 U42.4@7021.77,3929.6
NetC86_2: C86.2 R57.1 R175.2 U42.1 | length 767.6
  Top Layer w10: v1(6715,4040) 6759.38,4040 R57.1@6761.38,4042
  Bottom Layer w10: v1(6715,4040) 6818.11,3936.89 6818.11,3870.9 6919.01,3770 6967.72,3770 6997.72,3800 R175.2@6998.62,3800 C86.2@6998.58,3868 C86.2@6998.58,3868 6999.53,3868 7028.09,3896.56 7045.75,3896.56 7047.05,3897.86 7047.86,3897.86 7065.87,3915.87 7065.87,3966.62 7094.88,3995.62 7109.45,3995.62 U42.1@7118.23,4004.4
NetC105_1: C105.1 L2.4 U17.1
  other v2: 5905,3250
NetC105_2: C105.2 L2.3 U17.2 | length 77.9
  Bottom Layer w10: C105.2@5820.81,3147.8 C105.2@5825.81,3152.8
  Bottom Layer w40: v2@5750,3147.8 C105.2@5820.81,3147.8
  other v2: 5740,3150
NetC106_1: C106.1 L1.4 U16.1
  other v2: 1350,3150 1350,3205
NetC106_2: C106.2 L1.3 U16.2
  other v2: 1090,3240 1092.89,3297.11
NetC135_1: C135.1 L4.4 U25.1
  other v2: 5905,2550
NetC135_2: C135.2 L4.3 U25.2 | length 77.9
  Bottom Layer w10: C135.2@5820.81,2447.8 C135.2@5825.81,2452.8
  Bottom Layer w40: v2@5750,2447.8 C135.2@5820.81,2447.8
  other v2: 5740,2450
NetC136_1: C136.1 L3.4 U24.1
  other v2: 1350,2450 1350,2505
NetC136_2: C136.2 L3.3 U24.2 | length 4.1
  Top Layer w10: L3.3@1090,2452.36 L3.3@1092.89,2455.26
  other v2: 1090,2540 1092.89,2597.11
NetC156_1: C156.1 L6.4 U29.1
  other v2: 5905,1850
NetC156_2: C156.2 L6.3 U29.2 | length 89.7
  Bottom Layer w10: C156.2@5820.81,1747.8 C156.2@5825.81,1752.8
  Bottom Layer w40: v2(5740,1750) 5820.11,1750 5820.81,1749.3 C156.2@5820.81,1747.8
NetC157_1: C157.1 L5.4 U28.1
  other v2: 1350,1750 1350,1805
NetC157_2: C157.2 L5.3 U28.2
  other v2: 1090,1840 1092.89,1897.11
NetC158_1: C158.1 R206.1 | length 78.2
  Bottom Layer w10: R206.1@6180.59,1480 6180.59,1525.32 6200.35,1545.08 C158.1@6200.35,1550
NetC159_1: C159.1 D4.1 Q1.1 Q1.2 Q1.3 R98.2 R100.2 | length 553.7
  Top Layer w10: R100.2@6250.62,1430 v1(6290,1430)
  Bottom Layer w10: C159.1@5783.18,1417.09 C159.1@5783.18,1425 ; v1(5900,1335) 5928.22,1306.78 5928.22,1290.86 5934.08,1285 6004.91,1285 6049.91,1330 6235,1330 6290,1385 v1(6290,1430)
  other v1: 5760,1360 5790,1360
NetC160_1: C160.1 R206.2 U35.2 | length 138.1
  Top Layer w10: U35.2@6114.29,1348.27 6114.29,1362.68 6120.34,1368.73 v1(6120.34,1373.33)
  Bottom Layer w10: C160.1@6119.58,1414.69 6120,1415.11 C160.1@6123.66,1415.11 ; v1(6120.34,1373.33) 6120.34,1395.92 C160.1@6131.42,1407 C160.1@6131.42,1407 R206.2@6131.38,1475
NetC169_1: C169.1 R209.2 R212.2 R215.1 | length 285.6
  Bottom Layer w10: C169.1@6988.58,1194 R209.2@6988.62,1263 7038.76,1262.96 7107.72,1194 R212.2@7108.62,1194 R215.1@7108.62,1126
NetC170_1: C170.1 R101.2 R211.1 U44.5 | length 495.1
  Top Layer w10: R101.2@7141.38,1363 7142.28,1363 7171.24,1391.96 7222.04,1391.96 7270.39,1343.6 7270.39,1281.7 7270,1281.31 v1(7270,1243.34)
  Bottom Layer w10: v1(7270,1243.34) 7228.58,1201.92 C170.1@7228.58,1126 7230.38,1127.8 7323.04,1127.8 U44.5@7325.83,1130.59
NetC171_1: C171.1 R218.2 R219.1 U44.2 U44.4 | length 727.2
  Bottom Layer w10: U44.2@7325.83,1053.82 7285.39,1053.82 7260.61,1029.04 7211.42,1029.04 7172.37,990 C171.1@7171.42,990 7160,978.58 7160,951.72 7119.78,911.5 7083.19,911.5 7066.5,928.19 7066.5,951.81 7083.19,968.5 7086.22,968.5 7107.72,990 R219.1@7108.62,990 R218.2@7108.62,1058 7109.53,1058 7139.51,1087.98 7262.98,1087.98 7280,1105 U44.4@7325.83,1105
NetC174_1: C174.1 R222.2 R223.2 U46.4 | length 317.6
  Bottom Layer w10: R222.2@7222,836.38 7289.09,836.38 7320.47,805 7400.63,805 7419.76,824.13 7428.62,824.13 7437.4,832.91 U46.4@7437.4,841.77 7498.61,841.77 R223.2@7501.38,839 R223.2@7498.8,836.42
NetC174_2: C174.2 R55.1 R222.1 U46.1 | length 3729.1
  Top Layer w10: R55.1@7238.62,4236 7239.53,4236 7290.6,4184.92 7295.38,4184.92 7333.5,4146.81 7333.5,3985.91 7329.39,3981.81 7329.39,3764.54 7328.71,3763.86 7328.71,3676.64 7378.86,3626.5 7378.86,3075 7340,3036.14 7340,2678.28 7445,2573.28 7445,1460 7318.5,1333.5 7318.5,1219.91 7290.09,1191.5 7275.18,1191.5 7250,1166.32 7250,977.14 v1(7295.25,931.89)
  Bottom Layer w10: R222.1@7222,893.62 C174.2@7290,893.58 C174.2@7290,893.58 7290,894.53 C174.2@7295.25,899.78 ; v1(7295.25,931.89) C174.2@7295.25,899.78 ; U46.1@7362.6,938.23 7333.7,938.23 C174.2@7295.25,899.78
NetC176_1: C176.1 R226.2 R227.2 U47.4 | length 355.5
  Bottom Layer w10: R226.2@7222,716.38 C176.1@7290,716.42 C176.1@7290,716.42 7300,706.42 7300,685 7322.13,662.87 7322.13,662.04 7344.26,639.91 7406.34,639.91 7422.34,655.91 7428.62,655.91 7437.4,664.69 U47.4@7437.4,673.54 7471.02,673.54 7500.47,703 R227.2@7501.38,703
NetC176_2: C176.2 R56.1 R226.1 U47.1 | length 3740.3
  Top Layer w10: R56.1@7238.62,4100 7239.53,4100 7309.39,4030.14 7309.39,3772.82 7308.71,3772.15 7308.71,3668.36 7358.86,3618.21 7358.86,3083.28 7320,3044.42 7320,2670 7420,2570 7420,1480 7298.5,1358.5 7298.5,1228.19 7281.81,1211.5 7266.9,1211.5 7230,1174.6 7230,957.63 7249.75,937.88 v1(7249.75,937.08)
  Bottom Layer w10: v1(7249.75,937.08) 7227.08,937.08 7225,935 7211.01,935 7180,903.99 7180,816.53 7222,774.53 R226.1@7222,773.62 R226.1@7222,773.62 C176.2@7290,773.58 7293.58,770 U47.1@7362.6,770
NetC182_1: C182.1 D19.2 L7.4
  other v1: 5990,405 6035,405
NetC182_2: C182.2 L7.3 U37.6 U37.7 U37.8 U37.9 U37.10 U37.11 | length 714.3
  Top Layer w10: v1(5855,225) 5859.6,225 5874.6,240 6005,240 6017.5,227.5 ; L7.3@5972.91,290 L7.3@5992.6,290 ; 6030,215 6017.5,227.5 ; 6095.86,380 6090,374.14 6090,270 6047.5,227.5 6017.5,227.5 ; 6120,215 6120,216.02 ; U37.7@6130.79,410.71 U37.7@6130.87,410.63 ; 6130.87,381.63 6132.5,380 ; U37.6@6150.47,388.23 U37.6@6150.47,410.71
  Top Layer w12: 6030,215 6120,215 6138.66,215 6150.47,226.81 U37.11@6150.47,249.29 ; 6095.86,380 6132.5,380 6142.24,380 U37.6@6150.47,388.23 ; 6120,216.02 6130.79,226.81 U37.10@6130.79,249.29 ; 6130.87,381.63 U37.7@6130.87,410.63
  Bottom Layer w10: C182.2@5845,278 C182.2@5845,280
  other v1: 5855,195
NetD1_2: D1.2 R190.1 | length 436
  Top Layer w10: D1.2@7461.34,3012 7461.34,3221.34 v1(7595,3355)
  Bottom Layer w10: R190.1@7558.62,3358 7561.62,3355 v1(7595,3355)
NetD2_2: D2.2 R191.1 | length 471.1
  Top Layer w10: D2.2@7461.34,2930 7500,2968.66 7500,3228.08 7556.92,3285 v1(7595,3285)
  Bottom Layer w10: R191.1@7558.62,3290 7563.62,3285 v1(7595,3285)
NetD3_2: D3.2 R192.1 | length 464.6
  Top Layer w10: D3.2@7461.34,2848 7525,2911.66 7525,3150 v1(7595,3220)
  Bottom Layer w10: R192.1@7558.62,3222 7560.62,3220 v1(7595,3220)
NetD4_2: D4.2 L8.2 U35.6 U35.7 U35.8 U35.9 U35.10 U35.11 | length 460.9
  Top Layer w10: v1(5965,1313.5) 5965,1308.9 5976.5,1297.4 5976.5,1291.5 ; 5975.86,1125 5970,1130.86 5970,1285 5976.5,1291.5 ; U35.7@6015.79,1325.71 6015.71,1325.63 6015.71,1292.2 6015,1291.5 ; U35.11@6035.39,1164.21 U35.11@6035.47,1164.29 ; U35.6@6035.47,1325.71 6035.47,1303.23 6023.74,1291.5 6015,1291.5 ; 5976.5,1291.5 6015,1291.5
  Top Layer w12: 5975.86,1125 5998.98,1125 ; U35.10@6015.79,1164.29 6015.79,1141.81 5998.98,1125 ; U35.11@6035.39,1164.21 6035.39,1130.86 6029.54,1125 5998.98,1125
  other v1: 5965,1345 5895,1375 5930,1375
NetD5_1: D5.1 Q1.4 R98.1 U35.3 | length 1065.8
  Top Layer w8: D5.1@6048.03,1420 6073.5,1420 6092.84,1400.66 6092.84,1356.37 6094.17,1355.04 6094.17,1326.06 U35.3@6094.53,1325.71
  Top Layer w10: Q1.4@5772.72,1290.7 5744.3,1290.7 5718.23,1316.77 5673.23,1316.77 5610,1380 5610,1430 5610,1505 5645.86,1540.86 5689.14,1540.86 5720,1510 6065.31,1510 6080,1495.31 6080,1448.57 6074.14,1442.72 6050.75,1442.72 6040,1431.97 6040,1428.03 D5.1@6048.03,1420
NetD6_2: D6.2 R207.2 | length 136.3
  Top Layer w10: D6.2@6686.34,1315 6704.96,1333.62 6704.96,1383.04 v1(6705,1383.08)
  Bottom Layer w10: R207.2@6704.1,1323 6705,1323.9 v1(6705,1383.08)
NetD7_2: D7.2 R210.1 | length 98.1
  Top Layer w10: D7.2@6686.34,1230 v1(6730,1230)
  Bottom Layer w10: R210.1@6675.51,1230 v1(6730,1230)
NetD8_2: D8.2 R213.1 | length 98.1
  Top Layer w10: D8.2@6686.34,1145 v1(6730,1145)
  Bottom Layer w10: R213.1@6675.51,1145 v1(6730,1145)
NetD9_2: D9.2 R216.2 | length 98.1
  Top Layer w10: D9.2@6686.34,1065 v1(6730,1065)
  Bottom Layer w10: R216.2@6675.51,1065 v1(6730,1065)
NetD13_2: D13.2 R178.1 R183.1 | length 133.2
  Bottom Layer w25: R183.1@6082.48,3665 6082.48,3700 ; R178.1@6082.48,3735 6082.48,3700 ; D13.2@6145.67,3700 6082.48,3700
NetD14_2: D14.2 R185.1 R188.1 | length 185.9
  Bottom Layer w10: D14.2@712.6,3698.03 D14.2@712.6,3700
  Bottom Layer w25: D14.2@712.6,3698.03 750.98,3659.65 R185.1@750.98,3600 R188.1@750.98,3530
NetD15_2: D15.2 R202.1 R203.1 | length 133.2
  Bottom Layer w25: R203.1@6082.48,2265 6082.48,2300 ; R202.1@6082.48,2335 6082.48,2300 ; D15.2@6145.67,2300 6082.48,2300
NetD16_2: D16.2 R200.1 R201.1 | length 185.9
  Bottom Layer w10: R201.1@750.98,2390.16 R201.1@750.98,2400
  Bottom Layer w25: D16.2@712.6,2300 712.6,2351.77 R201.1@750.98,2390.16 ; R201.1@750.98,2400 R200.1@750.98,2470
NetD17_2: D17.2 J11.2 Q4.4
NetD18_2: D18.2 J15.2 Q5.4
NetJ8_5: J8.5 R58.1 | length 1094.7
  Top Layer w10: R58.1@7238.62,3964 7239.53,3964 7289.39,3914.14 7289.39,3781.11 7275,3766.72 v1(7275,3465)
  Bottom Layer w10: v1(7275,3465) 7279.6,3465 7294.6,3450 J8.5@7837,3450
NetJ8_6: J8.6 R59.1 | length 1210.6
  Top Layer w10: R59.1@7238.62,3896 7238.62,3863.72 7244.48,3857.86 7262.95,3857.86 7269.39,3851.42 7269.39,3789.39 7246.5,3766.5 7246.5,3448.41 v1(7274.98,3419.94)
  Bottom Layer w10: v1(7274.98,3419.94) 7278.47,3419.94 7296.88,3401.54 7888.54,3401.54 J8.6@7937,3450
NetJ8_7: J8.7 R193.1 | length 661.2
  Bottom Layer w10: R193.1@7258.62,3200 7259.53,3200 7284.53,3175 7661.72,3175 7836.72,3350 J8.7@7837,3350
NetJ8_8: J8.8 R195.1 | length 768.8
  Bottom Layer w10: R195.1@7258.62,3133 7259.53,3133 7272.48,3145.96 7272.48,3146.86 7280.62,3155 7670,3155 7816.54,3301.54 7888.54,3301.54 J8.8@7937,3350
NetJ8_9: J8.9 R196.1 | length 656.7
  Bottom Layer w10: R196.1@7258.62,3066 7341.58,3066 7410.58,3135 7678.28,3135 7793.28,3250 J8.9@7832,3250 ; J8.9@7832,3245 J8.9@7837,3250
NetJ8_10: J8.10 R197.1 | length 782.8
  Bottom Layer w10: R197.1@7258.62,2998 7301.86,2998 7393.86,3090 7665,3090 7775,3200 7887,3200 J8.10@7937,3250
NetQ2_3: Q2.3 R104.1 | length 88.5
  Top Layer w10: Q2.3@7091.34,1120 Q2.3@7089.37,1120 7100.12,1130.75 7112.22,1130.75 7140.47,1159 R104.1@7141.38,1159 R104.1@7128.42,1146.04
NetQ4_1: Q4.1 R205.2 | length 141.3
  Bottom Layer w10: R205.2@7670,1899.76 7670,1907.69 7705,1942.69 7705,2026.38 Q4.1@7705.16,2026.54
NetQ5_1: Q5.1 R208.2 | length 149.5
  Bottom Layer w10: R208.2@7670,1280 7670,1281.34 7693.66,1305 7699.14,1305 7705,1310.86 7705,1411.61 Q5.1@7705.16,1411.77
NetQ6_4: Q6.4 Q7.4 R115.2 U36.10 | length 532.3
  Top Layer w8: U36.10@6785,490.27 v1(6785,545) ; U36.10@6785.91,489.37 U36.10@6797.09,489.37 ; U36.10@6808.16,489.37 6809.07,488.46 6845.01,488.46
  Top Layer w10: v1(6755,765) 6830,690 6830,625 6785,580 v1(6785,545) ; U36.10@6785,490.27 U36.10@6785.91,489.37 ; U36.10@6797.09,489.37 U36.10@6808.16,489.37 ; 6845.01,488.46 6875.47,458 R115.2@6876.38,458
  Bottom Layer w10: v1(6755,765) 6757.5,762.5 6805.63,762.5 Q6.4@6806.14,761.99 ; v1(6785,545) 6785,517.01 6792.01,510 Q7.4@6804.88,510
NetR14_2: R14.2 R18.1 | length 79.8
  Top Layer w10: R18.1@6940,7015.12 R14.2@6940,7094.88
NetR15_2: R15.2 R19.1 | length 79.8
  Top Layer w10: R19.1@7300,7015.12 R15.2@7300,7094.88
NetR16_2: R16.2 R20.1 | length 79.8
  Top Layer w10: R20.1@7660,7015.12 R16.2@7660,7094.88
NetR18_2: R18.2 R22.1 | length 79.8
  Top Layer w10: R22.1@6940,6825.12 R18.2@6940,6904.88
NetR19_2: R19.2 R23.1 | length 79.8
  Top Layer w10: R23.1@7300,6825.12 R19.2@7300,6904.88
NetR20_2: R20.2 R24.1 | length 79.8
  Top Layer w10: R24.1@7660,6825.12 R20.2@7660,6904.88
NetR22_2: R22.2 R26.1 | length 79.8
  Top Layer w10: R26.1@6940,6635.12 R22.2@6940,6714.88
NetR23_2: R23.2 R27.1 | length 79.8
  Top Layer w10: R27.1@7300,6635.12 R23.2@7300,6714.88
NetR24_2: R24.2 R28.1 | length 79.8
  Top Layer w10: R28.1@7660,6635.12 R24.2@7660,6714.88
NetR26_2: R26.2 R30.1 | length 79.8
  Top Layer w10: R30.1@6940,6445.12 R26.2@6940,6524.88
NetR27_2: R27.2 R31.1 | length 79.8
  Top Layer w10: R31.1@7300,6445.12 R27.2@7300,6524.88
NetR28_2: R28.2 R32.1 | length 79.8
  Top Layer w10: R32.1@7660,6445.12 R28.2@7660,6524.88
NetR30_2: R30.2 R34.1 | length 79.8
  Top Layer w10: R34.1@6940,6255.12 R30.2@6940,6334.88
NetR31_2: R31.2 R35.1 | length 79.8
  Top Layer w10: R35.1@7300,6255.12 R31.2@7300,6334.88
NetR32_2: R32.2 R36.1 | length 79.8
  Top Layer w10: R36.1@7660,6255.12 R32.2@7660,6334.88
NetR37_2: R37.2 U1.3 | length 79.1
  Top Layer w10: R37.2@6580,6011.38 6580,6010.47 6610.59,5979.88 6610.59,5966.18 6619.37,5957.4 U1.3@6628.23,5957.4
